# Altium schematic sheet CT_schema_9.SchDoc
size 402 x 220 mm
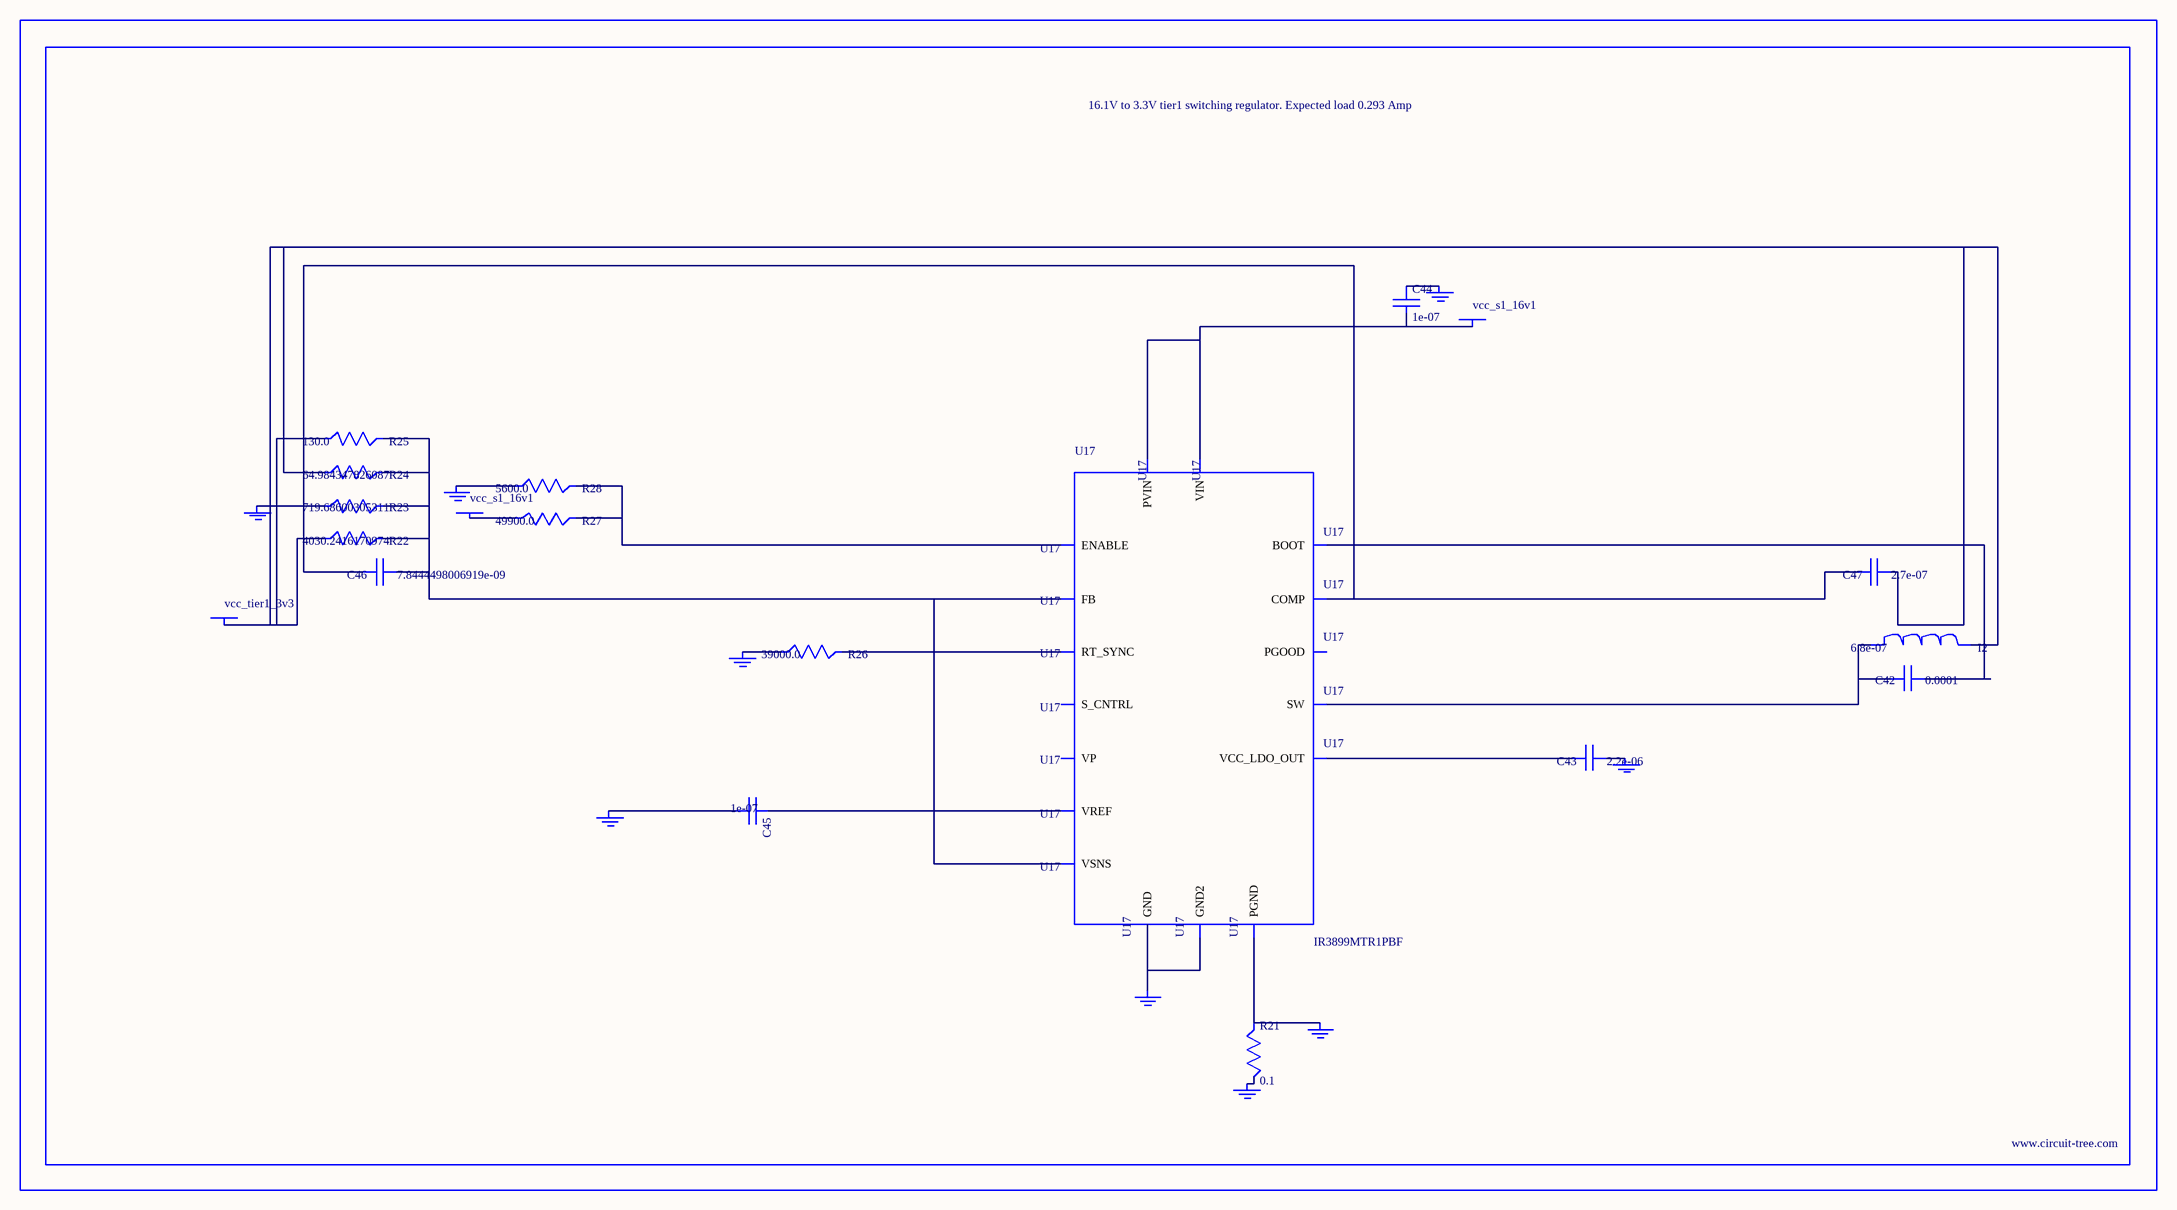
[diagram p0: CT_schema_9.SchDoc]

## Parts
BORDER8  (no value)
C42  0.0001  [C1210]
C43  2.2e-06  [C0603]
C44  1e-07  [C0402]
C45  1e-07  [C0402]
C46  7.8444498006919e-09  [R0603]
C47  2.7e-07  [C0603]
GND_INSTANCE_8_0  (no value)
GND_INSTANCE_8_1  (no value)
GND_INSTANCE_8_2  (no value)
GND_INSTANCE_8_3  (no value)
GND_INSTANCE_8_4  (no value)
GND_INSTANCE_8_5  (no value)
GND_INSTANCE_8_6  (no value)
GND_INSTANCE_8_7  (no value)
GND_INSTANCE_8_8  (no value)
I2  6.8e-07  [IND25X25CZ]
POWER_INSTANCE_8_0  vcc_s1_16v1
POWER_INSTANCE_8_1  vcc_s1_16v1
POWER_INSTANCE_8_2  vcc_tier1_3v3
R21  0.1  [R0603]
R22  4030.2416170974  [R0603]
R23  719.68600305311  [R0603]
R24  64.984347826087  [R0603]
R25  130.0  [R0603]
R26  39000.0  [R0603]
R27  49900.0  [R0603]
R28  5600.0  [R0603]
U17  IR3899MTR1PBF  [IR3899MTR1PBF]

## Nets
NetC42_1: C42.1 U17.14(BOOT)
NetC42_2: C42.2 I2.1 U17.12(SW)
NetC43_1: C43.1 GND_INSTANCE_8_4.0(GND)
NetC43_2: C43.2 U17.10(VCC_LDO_OUT)
NetC44_1: C44.1 GND_INSTANCE_8_3.0(GND)
NetC44_2: C44.2 POWER_INSTANCE_8_0.0(PWR) U17.9(VIN) U17.13(PVIN)
NetC45_1: C45.1 U17.2(VREF)
NetC45_2: C45.2 GND_INSTANCE_8_1.0(GND)
NetC46_1: C46.1 R22.2 R23.2 R24.2 R25.2 U17.1(FB) U17.8(VSNS)
NetC46_2: C46.2 C47.2 U17.3(COMP)
NetC47_1: C47.1 I2.2 POWER_INSTANCE_8_2.0(PWR) R22.1 R24.1 R25.1
NetGND_INSTANCE_8_0_0: GND_INSTANCE_8_0.0(GND) R23.1
NetGND_INSTANCE_8_2_0: GND_INSTANCE_8_2.0(GND) R26.1
NetGND_INSTANCE_8_5_0: GND_INSTANCE_8_5.0(GND) R21.2
NetGND_INSTANCE_8_6_0: GND_INSTANCE_8_6.0(GND) R21.1 U17.11(PGND)
NetGND_INSTANCE_8_7_0: GND_INSTANCE_8_7.0(GND) R28.1
NetGND_INSTANCE_8_8_0: GND_INSTANCE_8_8.0(GND) U17.4(GND) U17.17(GND2)
NetPOWER_INSTANCE_8_1_0: POWER_INSTANCE_8_1.0(PWR) R27.1
NetR26_2: R26.2 U17.5(RT_SYNC)
NetR27_2: R27.2 R28.2 U17.15(ENABLE)

Not connected (* = marked no-connect by the designer): U17 6(S_CNTRL) 7(PGOOD) 16(VP)

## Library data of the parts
BORDER8 = BORDER_PAGE8
C42 = GRM32ER61A107ME20L
C43 = C0603C225K8RACTU
C44 C45 = C0402C104K3RACTU
C46 = C46
C47 = C0603C274K3RAC
GND_INSTANCE_8_0-GND_INSTANCE_8_8 = GND
I2 = IHLP2525CZERR68M01
POWER_INSTANCE_8_0-POWER_INSTANCE_8_2 = PWR
R21 = ERJ-3RSFR10V
R22 = R22
R23 = R23
R24 = R24
R25 = RC0603JR-07130RL
R26 = RC0603JR-0739KL
R27 = RC0603FR-0749K9
R28 = RC0603JR-075K6L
